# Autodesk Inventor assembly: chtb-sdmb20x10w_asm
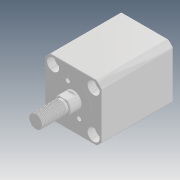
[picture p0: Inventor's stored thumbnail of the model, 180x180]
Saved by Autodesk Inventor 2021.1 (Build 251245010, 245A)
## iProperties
Company: Microsoft
Created: 2018-05
Part Number: chtb-sdmb20x10w_asm
Description: STEP AP214
Document SubType Name: Assembly
Designer: user
Title: chtb-sdmb20x10w_asm.STEP
Author: Windows
Revision Number: ÈÎºÎ
Sending System: SolidWorks 2015
Preprocessor: SwSTEP 2.0
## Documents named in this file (4)
- D:\Vault_2016\Projekty\Clamptek\Hydraulic\CHTB\CHTB-20\Inventor\CHTB-SDMB20x10W\chtb-sdmb20x10w_asm.iam
- D:\Vault_2016\Projekty\Clamptek\Hydraulic\CHTB\CHTB-20\Inventor\CHTB-SDMB20x10W\CHTB-SDMB20X10NBT.ipt
- D:\Vault_2016\Projekty\Clamptek\Hydraulic\CHTB\CHTB-20\Inventor\CHTB-SDMB20x10W\CHTB-SDMB20X10WHSG.ipt
- D:\Vault_2016\Projekty\Clamptek\Hydraulic\CHTB\CHTB-20\Inventor\CHTB-SDMB20x10W\QG_3.ipt
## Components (3 placed, 3 different names)
1. CHTB-SDMB20X10NBT_1
2. CHTB-SDMB20X10WHSG_2
3. QG_3_3
